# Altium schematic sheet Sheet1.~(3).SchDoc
size A; SheetNumber: 1; SheetTotal: 1
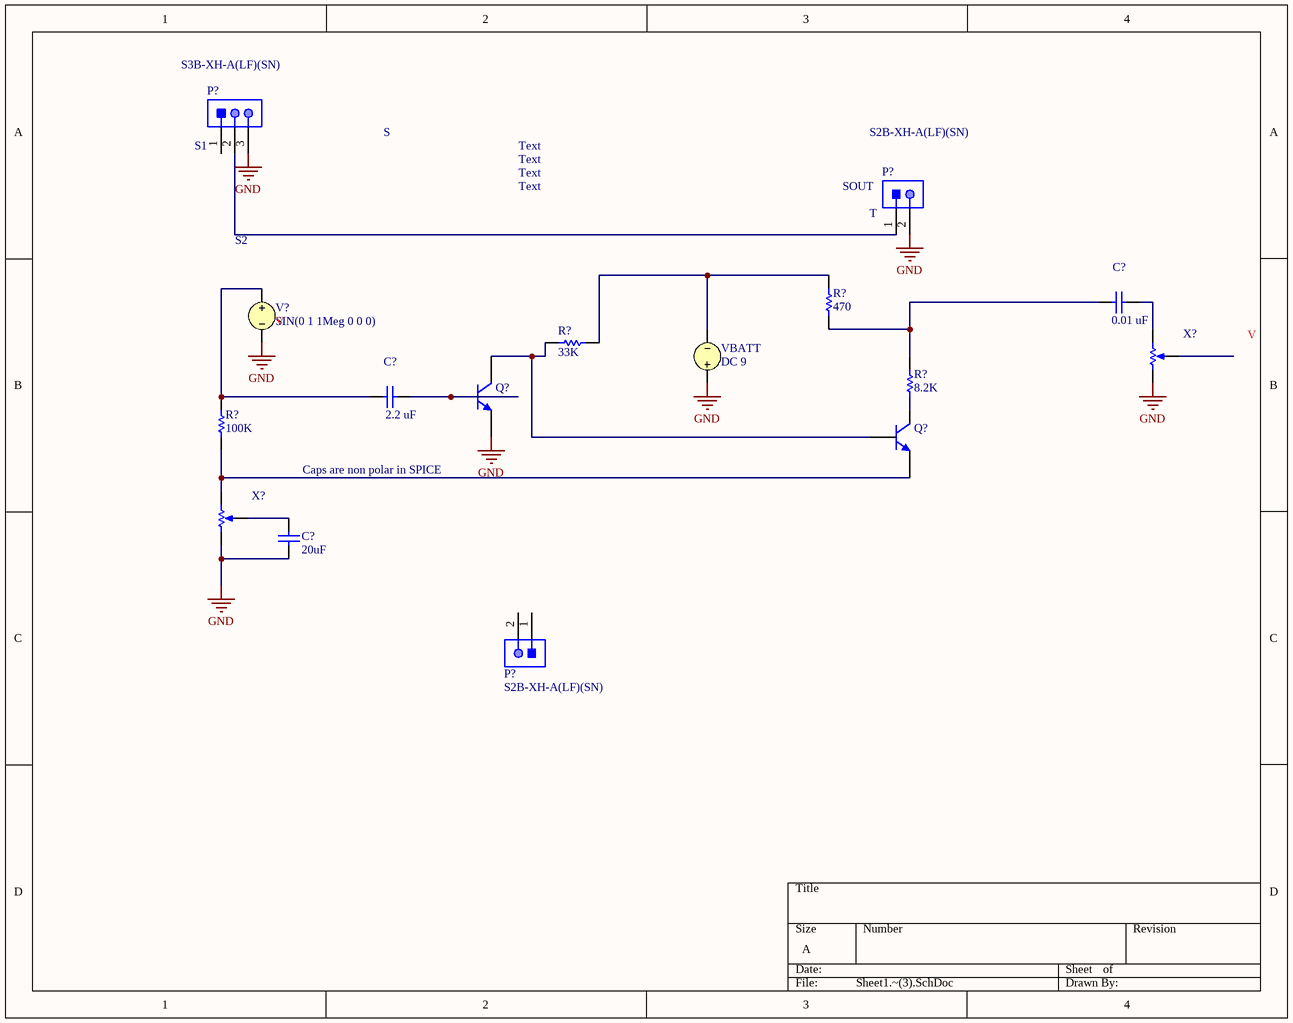
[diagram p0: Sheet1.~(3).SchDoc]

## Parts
(Parts that share a designator on the sheet are numbered #1, #2 ... from top to bottom, then left to right.)
C?#1  value 0.01 uF  (hidden comment: Capacitor)
C?#2  value 2.2 uF  (hidden comment: Capacitor)
C?#3  value 20uF  (hidden comment: Capacitor)
P?#1  S3B-XH-A(LF)(SN)  [JST-S3B-XH-A(LF)(SN)_V]
P?#2  S2B-XH-A(LF)(SN)  [JST-S2B-XH-A(LF)(SN)_V]
P?#3  S2B-XH-A(LF)(SN)  [JST-S2B-XH-A(LF)(SN)_V]
Q?#1  Bipolar NPN 3 Pins Transistor Modified Version of the Gummel-Poon Model  (value not drawn)
Q?#2  Bipolar NPN 3 Pins Transistor Modified Version of the Gummel-Poon Model  (value not drawn)
R?#1  value 470  (hidden comment: Resistor)
R?#2  value 33K  (hidden comment: Resistor)
R?#3  value 8.2K  (hidden comment: Resistor)
R?#4  value 100K  (hidden comment: Resistor)
V?  SIN(0 1 1Meg 0 0 0)
VBATT  DC 9
X?#1  Potentiometer  (value not drawn)
X?#2  Potentiometer  (value not drawn)

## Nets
GND: C?#3.1 P?#1.3 P?#2.2 Q?#1.3(E) V?.2 VBATT.1 X?#1.1(TOP) X?#2.1(TOP)
NetC?#1_1: C?#1.1 R?#1.1 R?#3.1
NetC?#1_2: C?#1.2 X?#1.2(BOT)
NetC?#2_1: C?#2.1 R?#4.2 V?.1
NetC?#2_2: C?#2.2 Q?#1.2(B)
NetC?#3_2: C?#3.2 X?#2.3(TAP)
NetP?#1_2: P?#1.2 P?#2.1
NetQ?#1_1: Q?#1.1(C) Q?#2.2(B) R?#2.2
NetQ?#2_1: Q?#2.1(C) R?#3.2
NetQ?#2_3: Q?#2.3(E) R?#4.1 X?#2.2(BOT)
NetR?#1_2: R?#1.2 R?#2.1 VBATT.2

Not connected (* = marked no-connect by the designer): P?#1 1; P?#3 1 2; X?#1 3(TAP)

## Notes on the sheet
- (near P?#1) S1
- S
- Text
- (near P?#2) SOUT
- (near P?#2) T
- S2
- Caps are non polar in SPICE

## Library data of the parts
C?#1-C?#3 = Capacitor: SimulationGenericComponent: True
P?#1 = CMP-002-00033-2: Male Header, Pitch 2.5 mm, 1 x 3 Position, Height 6.1 mm, Tail Length 3.4 mm, -25 to 85 degC, RoHS, Bulk; Manufacturer: JST
P?#2 P?#3 = CMP-002-00032-2: Male Header, Pitch 2.5 mm, 1 x 2 Position, Height 6.1 mm, Tail Length 3.4 mm, -25 to 85 degC, RoHS, Bulk; Manufacturer: JST
Q?#1 Q?#2 = BJT NPN_MGP: BF: 100; AF: 0; BR: 1; EG: 1.11; FC: 0.5; IS: 1e-16; MJC: 0.33; NC: 2; NE: 1.5; TNOM: 27; VBC_MAX: 1e99; VJC: 0.75; XTI: 3; SimulationGenericComponent: True
R?#1-R?#4 = Resistor: TC1: 0; SimulationGenericComponent: True
V? = VSRC: Voltage Source; Note: PCB Footprint - Not required; AC Magnitude: 1; AC Phase: 0; DC Magnitude: 5
VBATT = VSRC: Voltage Source; Note: PCB Footprint - Not required; AC Magnitude: 1; AC Phase: 0; Value: 9
X?#1 = Potentiometer: value: 500k; position: 0.5; SimulationGenericComponent: True
X?#2 = Potentiometer: value: 1k; position: 0.5; SimulationGenericComponent: True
